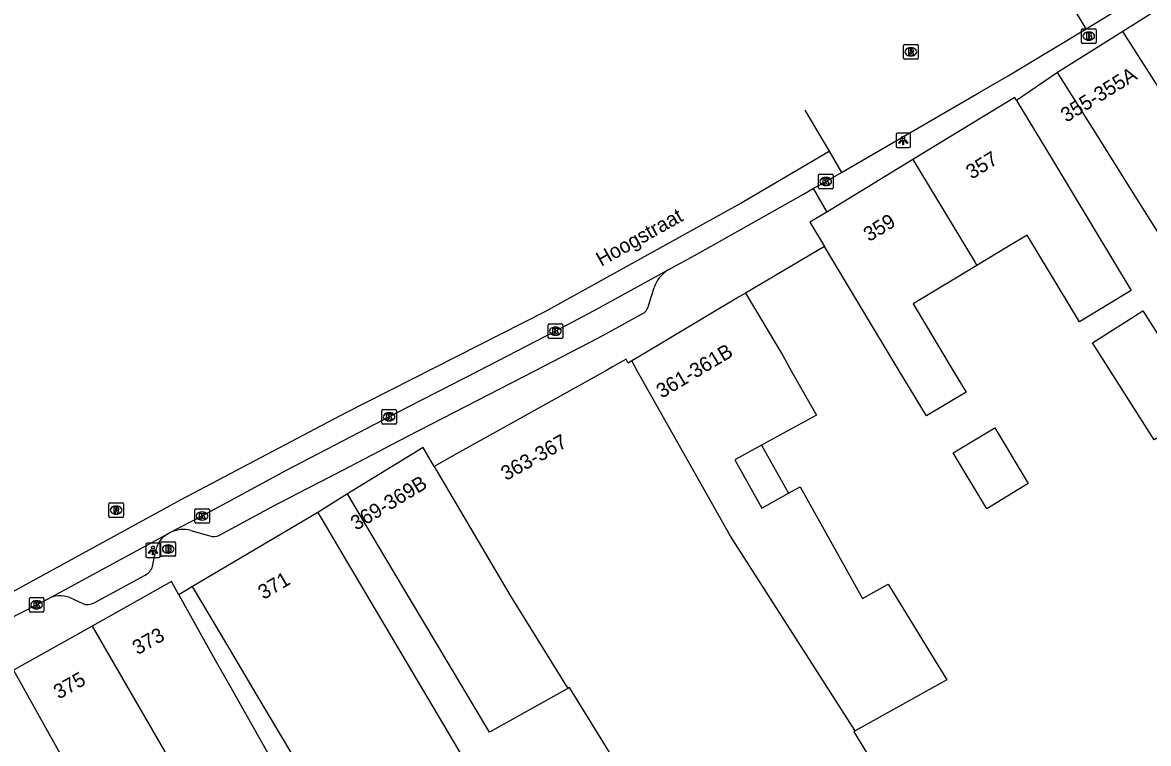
# Model space of a CAD drawing. Extents: x 159822 to 160765, y 380693 to 381634.
# Drawn here: x 159932.4 to 160009.6, y 381474.4 to 381523.9 of the extents above; entities that cross this region are included whole.
import ezdxf

# ---------------------------------------------------------------- set-up
doc = ezdxf.new("R2010")
doc.units = 0
for name, color, linetype in [('IMGEO_Brandkraan', 7, 'Continuous'), ('IMGEO_Kolk', 7, 'Continuous'), ('IMGEO_Lichtpunt', 7, 'Continuous'), ('IMGEO_Openbare_ruimte_label', 7, 'Continuous'), ('IMGEO_Pand', 7, 'Continuous'), ('IMGEO_Pand_nummerreeks', 7, 'Continuous'), ('IMGEO_Rijbaan_lokaal_gesloten', 7, 'Continuous'), ('IMGEO_Rijbaan_lokaal_open', 7, 'Continuous'), ('IMGEO_Rioolput', 7, 'Continuous'), ('IMGEO_Voetpad_open', 7, 'Continuous')]:
    doc.layers.add(name, color=color, linetype=linetype)

msp = doc.modelspace()

# ---------------------------------------------------------------- linework, layer by layer
at = {"layer": 'IMGEO_Brandkraan'}
for p, q in [((160005.025, 381522.533), (160005.025, 381523.385)), ((160005.1, 381523.459), (160005.952, 381523.459)), ((160005.513, 381523.239), (160005.538, 381523.239)), ((160006.026, 381523.385), (160006.026, 381522.533)), ((160005.952, 381522.459), (160005.1, 381522.459)), ((160005.536, 381522.679), (160005.511, 381522.679)), ((159941.871, 381487.334), (159941.871, 381488.186)), ((159941.946, 381488.26), (159942.798, 381488.26)), ((159942.359, 381488.04), (159942.384, 381488.04)), ((159942.872, 381488.186), (159942.872, 381487.334)), ((159942.798, 381487.26), (159941.946, 381487.26)), ((159942.382, 381487.48), (159942.357, 381487.48))]:
    msp.add_line(p, q, dxfattribs=at)
for points in [[(160005.025, 381522.533), (160005.025, 381523.385)], [(160005.1, 381523.459), (160005.952, 381523.459)], [(160005.373, 381523.159), (160005.373, 381522.759), (160005.586, 381522.759)], [(160005.604, 381523.159), (160005.373, 381523.159)], [(160005.552, 381523.078), (160005.498, 381523.078), (160005.498, 381523.002)], [(160005.498, 381523.002), (160005.551, 381523.002)], [(160005.56, 381522.926), (160005.498, 381522.926), (160005.498, 381522.845)], [(160005.498, 381522.845), (160005.56, 381522.845)], [(160006.026, 381523.385), (160006.026, 381522.533)], [(160005.952, 381522.459), (160005.1, 381522.459)], [(159941.871, 381487.334), (159941.871, 381488.186)], [(159941.946, 381488.26), (159942.798, 381488.26)], [(159942.219, 381487.96), (159942.219, 381487.56), (159942.432, 381487.56)], [(159942.45, 381487.96), (159942.219, 381487.96)], [(159942.872, 381488.186), (159942.872, 381487.334)], [(159942.798, 381487.26), (159941.946, 381487.26)], [(159942.398, 381487.879), (159942.344, 381487.879), (159942.344, 381487.803)], [(159942.344, 381487.803), (159942.397, 381487.803)], [(159942.406, 381487.727), (159942.344, 381487.727), (159942.344, 381487.646)], [(159942.344, 381487.646), (159942.406, 381487.646)]]:
    msp.add_lwpolyline(points, dxfattribs=at)
for centre, radius, start, end in [((160005.102, 381523.383), 0.0765, 91.55205, 178.44795), ((160005.102, 381523.383), 0.0765, 91.55205, 178.44795), ((160005.553, 381523.04), 0.0379, 267.82845, 90.93552), ((160005.561, 381522.885), 0.0404, 269.87594, 90.50774), ((160005.592, 381523.01), 0.251, 268.66757, 293.53466), ((160005.608, 381523.014), 0.145, 59.4692, 91.53667), ((160005.633, 381523.061), 0.0922, 285.51372, 58.15012), ((160005.638, 381522.869), 0.105, 301.31148, 78.98903), ((160005.95, 381523.383), 0.0765, 1.55205, 88.44795), ((160005.95, 381523.383), 0.0765, 1.55205, 88.44795), ((160005.102, 381522.535), 0.0765, 181.55205, 268.44795), ((160005.102, 381522.535), 0.0765, 181.55205, 268.44795), ((160005.95, 381522.535), 0.0765, 271.55205, 358.44795), ((160005.95, 381522.535), 0.0765, 271.55205, 358.44795), ((159941.948, 381488.184), 0.0765, 91.55205, 178.44795), ((159941.948, 381488.184), 0.0765, 91.55205, 178.44795), ((159942.454, 381487.815), 0.145, 59.4692, 91.53667), ((159942.796, 381488.184), 0.0765, 1.55205, 88.44795), ((159942.796, 381488.184), 0.0765, 1.55205, 88.44795), ((159941.948, 381487.336), 0.0765, 181.55205, 268.44795), ((159941.948, 381487.336), 0.0765, 181.55205, 268.44795), ((159942.399, 381487.841), 0.0379, 267.82845, 90.93552), ((159942.407, 381487.686), 0.0404, 269.87594, 90.50774), ((159942.438, 381487.811), 0.251, 268.66757, 293.53466), ((159942.479, 381487.862), 0.0922, 285.51372, 58.15012), ((159942.484, 381487.67), 0.105, 301.31148, 78.98903), ((159942.796, 381487.336), 0.0765, 271.55205, 358.44795), ((159942.796, 381487.336), 0.0765, 271.55205, 358.44795)]:
    msp.add_arc(centre, radius, start, end, dxfattribs=at)
for centre, major_axis, ratio, start_param, end_param in [((160005.512, 381522.959), (-0.387, 0.002), 0.722429, 4.712389, 7.853982), ((160005.537, 381522.959), (-0.39, 0.002), 0.717154, 1.570796, 4.712389), ((159942.358, 381487.76), (-0.387, 0.002), 0.722429, 4.712389, 7.853982), ((159942.383, 381487.76), (-0.39, 0.002), 0.717154, 1.570796, 4.712389)]:
    msp.add_ellipse(centre, major_axis=major_axis, ratio=ratio, start_param=start_param, end_param=end_param, dxfattribs=at)
at = {"layer": 'IMGEO_Kolk'}
for p, q in [((159987.059, 381513.483), (159987.911, 381513.483)), ((159986.984, 381512.557), (159986.984, 381513.409)), ((159987.495, 381512.703), (159987.47, 381512.703)), ((159987.472, 381513.263), (159987.497, 381513.263)), ((159987.985, 381513.409), (159987.985, 381512.557)), ((159987.911, 381512.483), (159987.059, 381512.483)), ((159968.432, 381502.28), (159968.432, 381503.132)), ((159968.507, 381503.206), (159969.359, 381503.206)), ((159968.92, 381502.986), (159968.945, 381502.986)), ((159969.433, 381503.132), (159969.433, 381502.28)), ((159969.359, 381502.206), (159968.507, 381502.206)), ((159968.943, 381502.426), (159968.918, 381502.426)), ((159957.023, 381496.41), (159957.023, 381497.262)), ((159957.098, 381497.336), (159957.95, 381497.336)), ((159958.024, 381497.262), (159958.024, 381496.41)), ((159957.534, 381496.556), (159957.509, 381496.556)), ((159957.511, 381497.116), (159957.536, 381497.116)), ((159957.95, 381496.336), (159957.098, 381496.336)), ((159944.193, 381489.601), (159944.193, 381490.453)), ((159944.268, 381490.527), (159945.12, 381490.527)), ((159944.681, 381490.307), (159944.706, 381490.307)), ((159945.194, 381490.453), (159945.194, 381489.601)), ((159945.12, 381489.527), (159944.268, 381489.527)), ((159944.704, 381489.747), (159944.679, 381489.747)), ((159932.844, 381483.51), (159932.844, 381484.362)), ((159932.919, 381484.436), (159933.771, 381484.436)), ((159933.332, 381484.216), (159933.357, 381484.216)), ((159933.845, 381484.362), (159933.845, 381483.51)), ((159933.771, 381483.436), (159932.919, 381483.436)), ((159933.355, 381483.656), (159933.33, 381483.656))]:
    msp.add_line(p, q, dxfattribs=at)
for points in [[(159987.059, 381513.483), (159987.911, 381513.483)], [(159986.984, 381512.557), (159986.984, 381513.409)], [(159987.305, 381513.183), (159987.428, 381513.183), (159987.428, 381513.032), (159987.558, 381513.183), (159987.722, 381513.183), (159987.576, 381513.032), (159987.729, 381512.783), (159987.577, 381512.783), (159987.492, 381512.947), (159987.428, 381512.88), (159987.428, 381512.783), (159987.305, 381512.783), (159987.305, 381513.183)], [(159987.985, 381513.409), (159987.985, 381512.557)], [(159987.911, 381512.483), (159987.059, 381512.483)], [(159968.432, 381502.28), (159968.432, 381503.132)], [(159968.507, 381503.206), (159969.359, 381503.206)], [(159968.753, 381502.906), (159968.876, 381502.906), (159968.876, 381502.755), (159969.006, 381502.906), (159969.17, 381502.906), (159969.024, 381502.755), (159969.177, 381502.506), (159969.025, 381502.506), (159968.94, 381502.67), (159968.876, 381502.603), (159968.876, 381502.506), (159968.753, 381502.506), (159968.753, 381502.906)], [(159969.433, 381503.132), (159969.433, 381502.28)], [(159969.359, 381502.206), (159968.507, 381502.206)], [(159957.023, 381496.41), (159957.023, 381497.262)], [(159957.098, 381497.336), (159957.95, 381497.336)], [(159958.024, 381497.262), (159958.024, 381496.41)], [(159957.344, 381497.036), (159957.467, 381497.036), (159957.467, 381496.885), (159957.597, 381497.036), (159957.761, 381497.036), (159957.615, 381496.885), (159957.768, 381496.636), (159957.616, 381496.636), (159957.531, 381496.8), (159957.467, 381496.733), (159957.467, 381496.636), (159957.344, 381496.636), (159957.344, 381497.036)], [(159957.95, 381496.336), (159957.098, 381496.336)], [(159944.193, 381489.601), (159944.193, 381490.453)], [(159944.268, 381490.527), (159945.12, 381490.527)], [(159945.194, 381490.453), (159945.194, 381489.601)], [(159945.12, 381489.527), (159944.268, 381489.527)], [(159944.514, 381490.227), (159944.637, 381490.227), (159944.637, 381490.076), (159944.767, 381490.227), (159944.931, 381490.227), (159944.785, 381490.076), (159944.938, 381489.827), (159944.786, 381489.827), (159944.701, 381489.991), (159944.637, 381489.924), (159944.637, 381489.827), (159944.514, 381489.827), (159944.514, 381490.227)], [(159932.844, 381483.51), (159932.844, 381484.362)], [(159932.919, 381484.436), (159933.771, 381484.436)], [(159933.165, 381484.136), (159933.288, 381484.136), (159933.288, 381483.985), (159933.418, 381484.136), (159933.582, 381484.136), (159933.436, 381483.985), (159933.589, 381483.736), (159933.437, 381483.736), (159933.352, 381483.9), (159933.288, 381483.833), (159933.288, 381483.736), (159933.165, 381483.736), (159933.165, 381484.136)], [(159933.845, 381484.362), (159933.845, 381483.51)], [(159933.771, 381483.436), (159932.919, 381483.436)]]:
    msp.add_lwpolyline(points, dxfattribs=at)
for centre, start, end in [((159987.061, 381513.407), 91.55205, 178.44795), ((159987.061, 381513.407), 91.55205, 178.44795), ((159987.909, 381513.407), 1.55205, 88.44795), ((159987.909, 381513.407), 1.55205, 88.44795), ((159987.061, 381512.559), 181.55205, 268.44795), ((159987.061, 381512.559), 181.55205, 268.44795), ((159987.909, 381512.559), 271.55205, 358.44795), ((159987.909, 381512.559), 271.55205, 358.44795), ((159968.509, 381503.13), 91.55205, 178.44795), ((159968.509, 381503.13), 91.55205, 178.44795), ((159969.357, 381503.13), 1.55205, 88.44795), ((159969.357, 381503.13), 1.55205, 88.44795), ((159968.509, 381502.282), 181.55205, 268.44795), ((159968.509, 381502.282), 181.55205, 268.44795), ((159969.357, 381502.282), 271.55205, 358.44795), ((159969.357, 381502.282), 271.55205, 358.44795), ((159957.1, 381497.26), 91.55205, 178.44795), ((159957.1, 381497.26), 91.55205, 178.44795), ((159957.948, 381497.26), 1.55205, 88.44795), ((159957.948, 381497.26), 1.55205, 88.44795), ((159957.1, 381496.412), 181.55205, 268.44795), ((159957.1, 381496.412), 181.55205, 268.44795), ((159957.948, 381496.412), 271.55205, 358.44795), ((159957.948, 381496.412), 271.55205, 358.44795), ((159944.27, 381490.451), 91.55205, 178.44795), ((159944.27, 381490.451), 91.55205, 178.44795), ((159945.118, 381490.451), 1.55205, 88.44795), ((159945.118, 381490.451), 1.55205, 88.44795), ((159944.27, 381489.603), 181.55205, 268.44795), ((159944.27, 381489.603), 181.55205, 268.44795), ((159945.118, 381489.603), 271.55205, 358.44795), ((159945.118, 381489.603), 271.55205, 358.44795), ((159932.921, 381484.36), 91.55205, 178.44795), ((159932.921, 381484.36), 91.55205, 178.44795), ((159933.769, 381484.36), 1.55205, 88.44795), ((159933.769, 381484.36), 1.55205, 88.44795), ((159932.921, 381483.512), 181.55205, 268.44795), ((159932.921, 381483.512), 181.55205, 268.44795), ((159933.769, 381483.512), 271.55205, 358.44795), ((159933.769, 381483.512), 271.55205, 358.44795)]:
    msp.add_arc(centre, 0.0765, start, end, dxfattribs=at)
for centre, major_axis, ratio, start_param, end_param in [((159987.471, 381512.983), (-0.387, 0.002), 0.722429, 4.712389, 7.853982), ((159987.496, 381512.983), (-0.39, 0.002), 0.717154, 1.570796, 4.712389), ((159968.919, 381502.706), (-0.387, 0.002), 0.722429, 4.712389, 7.853982), ((159968.944, 381502.706), (-0.39, 0.002), 0.717154, 1.570796, 4.712389), ((159957.51, 381496.836), (-0.387, 0.002), 0.722429, 4.712389, 7.853982), ((159957.535, 381496.836), (-0.39, 0.002), 0.717154, 1.570796, 4.712389), ((159944.68, 381490.027), (-0.387, 0.002), 0.722429, 4.712389, 7.853982), ((159944.705, 381490.027), (-0.39, 0.002), 0.717154, 1.570796, 4.712389), ((159933.331, 381483.936), (-0.387, 0.002), 0.722429, 4.712389, 7.853982), ((159933.356, 381483.936), (-0.39, 0.002), 0.717154, 1.570796, 4.712389)]:
    msp.add_ellipse(centre, major_axis=major_axis, ratio=ratio, start_param=start_param, end_param=end_param, dxfattribs=at)
at = {"layer": 'IMGEO_Lichtpunt'}
for p, q in [((159992.302, 381516.205), (159992.302, 381515.398)), ((159992.302, 381516.205), (159992.302, 381515.398)), ((159993.204, 381516.3), (159992.396, 381516.3)), ((159993.204, 381516.3), (159992.396, 381516.3)), ((159993.298, 381515.398), (159993.298, 381516.205)), ((159993.298, 381515.398), (159993.298, 381516.205)), ((159992.396, 381515.304), (159993.204, 381515.304)), ((159992.396, 381515.304), (159993.204, 381515.304)), ((159940.826, 381488.072), (159940.826, 381487.265)), ((159940.826, 381488.072), (159940.826, 381487.265)), ((159941.728, 381488.167), (159940.92, 381488.167)), ((159941.728, 381488.167), (159940.92, 381488.167)), ((159941.822, 381487.265), (159941.822, 381488.072)), ((159941.822, 381487.265), (159941.822, 381488.072)), ((159940.92, 381487.171), (159941.728, 381487.171)), ((159940.92, 381487.171), (159941.728, 381487.171))]:
    msp.add_line(p, q, dxfattribs=at)
for points in [[(159992.676, 381515.869), (159992.715, 381515.841), (159992.527, 381515.579), (159992.489, 381515.606), (159992.676, 381515.869)], [(159992.778, 381515.821), (159992.825, 381515.821), (159992.825, 381515.499), (159992.778, 381515.499), (159992.778, 381515.821)], [(159992.888, 381515.841), (159992.926, 381515.868), (159993.113, 381515.606), (159993.074, 381515.578), (159992.888, 381515.841)], [(159941.2, 381487.736), (159941.239, 381487.708), (159941.051, 381487.446), (159941.013, 381487.473), (159941.2, 381487.736)], [(159941.302, 381487.688), (159941.349, 381487.688), (159941.349, 381487.366), (159941.302, 381487.366), (159941.302, 381487.688)], [(159941.412, 381487.708), (159941.45, 381487.735), (159941.637, 381487.473), (159941.598, 381487.445), (159941.412, 381487.708)]]:
    msp.add_lwpolyline(points, dxfattribs=at)
for centre in [(159992.801, 381516.003), (159941.325, 381487.87)]:
    msp.add_circle(centre, 0.0994, dxfattribs=at)
for centre, start, end in [((159992.396, 381516.205), 90, 180), ((159992.396, 381516.205), 90, 180), ((159993.204, 381516.205), 0, 90), ((159993.204, 381516.205), 0, 90), ((159992.396, 381515.398), 180, 270), ((159992.396, 381515.398), 180, 270), ((159993.204, 381515.398), 270, 0), ((159993.204, 381515.398), 270, 360), ((159940.92, 381488.072), 90, 180), ((159940.92, 381488.072), 90, 180), ((159941.728, 381488.072), 0, 90), ((159941.728, 381488.072), 0, 90), ((159940.92, 381487.265), 180, 270), ((159940.92, 381487.265), 180, 270), ((159941.728, 381487.265), 270, 0), ((159941.728, 381487.265), 270, 360)]:
    msp.add_arc(centre, 0.0946, start, end, dxfattribs=at)
at = {"layer": 'IMGEO_Pand'}
for points in [[(160014.641, 381527.565), (160014.041, 381527.185), (160007.851, 381523.273)], [(160007.851, 381523.273), (160003.39, 381520.454)], [(160012.891, 381515.416), (160007.851, 381523.273)], [(160023.877, 381495.766), (160020.325, 381493.529), (160016.251, 381500), (160008.062, 381513.006), (160006.05, 381516.226), (160003.39, 381520.454)], [(160000.573, 381518.549), (160000.452, 381518.75), (160000, 381518.475), (159993.462, 381514.491)], [(160000.573, 381518.549), (160003.033, 381514.469), (160008.438, 381505.504), (160004.88, 381503.359), (160001.299, 381509.3), (160000, 381508.517), (159997.853, 381507.222)], [(159993.462, 381514.491), (159987.549, 381510.887)], [(159993.462, 381514.491), (159997.728, 381507.415), (159997.853, 381507.222)], [(159987.549, 381510.887), (159986.387, 381510.179), (159987.393, 381508.511)], [(159997.853, 381507.222), (159993.468, 381504.578), (159996.217, 381500), (159997.103, 381498.525), (159994.391, 381496.892), (159992.52, 381500), (159989.934, 381504.296), (159987.393, 381508.511)], [(159981.967, 381505.328), (159981.489, 381505.041), (159974.614, 381500.916), (159974.177, 381500.666)], [(159981.967, 381505.328), (159984.528, 381501.034), (159985.116, 381500), (159986.856, 381496.937), (159983.074, 381494.884)], [(160010.01, 381495.246), (160005.773, 381501.901), (160009.243, 381504.11), (160013.556, 381497.336), (160010.01, 381495.246)], [(159974.177, 381500.666), (159973.927, 381500.523), (159973.777, 381500.79), (159972.86, 381500.263), (159972.389, 381500), (159962.159, 381494.282), (159960.772, 381493.507), (159960.626, 381493.425)], [(159989.504, 381475.275), (159980.953, 381488.644), (159974.553, 381500), (159974.177, 381500.666)], [(159998.526, 381490.509), (159996.224, 381494.373), (159999.082, 381496.075), (160001.357, 381492.256), (159998.526, 381490.509)], [(159960.626, 381493.425), (159959.863, 381494.724), (159954.663, 381491.547)], [(159983.074, 381494.884), (159981.233, 381493.885), (159983.091, 381490.562), (159984.919, 381491.584)], [(159983.074, 381494.884), (159984.919, 381491.584)], [(159960.626, 381493.425), (159965.835, 381484.562), (159969.777, 381478.193)], [(159984.919, 381491.584), (159985.721, 381492.032), (159990.003, 381484.372), (159991.772, 381485.36), (159995.785, 381478.787), (159989.504, 381475.275)], [(159969.777, 381478.193), (159964.414, 381475.194), (159957.17, 381487.344), (159954.663, 381491.547)], [(159952.629, 381490.261), (159955.179, 381485.96), (159963.025, 381472.729), (159965.093, 381469.241), (159960.942, 381466.779), (159958.874, 381470.267), (159956.844, 381473.69), (159952.421, 381471.068), (159948.483, 381477.709), (159946.592, 381480.898), (159944.042, 381485.199)], [(159952.629, 381490.261), (159944.042, 381485.199)], [(159943.094, 381484.616), (159942.586, 381485.527), (159937.151, 381482.476)], [(159943.094, 381484.616), (159945.573, 381480.173), (159946.58, 381478.421), (159951.006, 381470.546), (159949.258, 381469.678), (159949.545, 381469.151)], [(159937.151, 381482.476), (159931.762, 381479.45)], [(159937.151, 381482.476), (159945.986, 381467.216)], [(159931.762, 381479.45), (159935.718, 381472.36)], [(159989.504, 381475.275), (159989.4, 381475.217), (159996.739, 381463.236), (159983.663, 381455.926), (159969.908, 381478.266), (159969.777, 381478.193)]]:
    msp.add_lwpolyline(points, dxfattribs=at)
at = {"layer": 'IMGEO_Rijbaan_lokaal_gesloten'}
for points in [[(160005.352, 381523.447), (160008.094, 381525.124), (160011.607, 381527.279), (160015.114, 381529.478), (160015.964, 381530.015), (160025.094, 381535.855), (160026.107, 381536.518), (160029.867, 381538.931), (160042.646, 381547.078), (160046.466, 381549.511)], [(160005.352, 381523.447), (160004.479, 381524.903)], [(159988.557, 381513.599), (159998.058, 381519.1), (160000, 381520.239), (160001.104, 381520.886), (160005.352, 381523.447)], [(159986.055, 381517.88), (159987.706, 381515.056)], [(159825.741, 381425.114), (159830.92, 381427.938), (159857.238, 381442.392), (159881.509, 381456.068), (159898.004, 381465.69), (159907.745, 381471.382), (159914.294, 381475.19), (159926.777, 381482.151), (159943.271, 381491.16), (159954.568, 381497.138), (159968.238, 381504.058), (159981.458, 381511.387), (159987.706, 381515.056)], [(159987.706, 381515.056), (159988.557, 381513.599)]]:
    msp.add_lwpolyline(points, dxfattribs=at)
at = {"layer": 'IMGEO_Rijbaan_lokaal_open'}
for points in [[(159986.624, 381512.501), (159987.48, 381512.983), (159988.557, 381513.599)], [(159976.668, 381506.91), (159978.262, 381507.78), (159979.817, 381508.648), (159985.965, 381512.122), (159986.624, 381512.501)], [(159942.487, 381488.885), (159944.694, 381490.028), (159948.597, 381492.138), (159950.445, 381493.14), (159958.832, 381497.52), (159963.66, 381500), (159968.928, 381502.706), (159971.586, 381504.125), (159976.668, 381506.91)], [(159934.089, 381484.332), (159942.338, 381488.805)], [(159942.338, 381488.805), (159942.487, 381488.885)], [(159928.594, 381481.394), (159931.412, 381482.953), (159933.344, 381483.936), (159934.089, 381484.332)]]:
    msp.add_lwpolyline(points, dxfattribs=at)
at = {"layer": 'IMGEO_Rioolput'}
for p, q in [((159992.816, 381521.452), (159992.816, 381522.304)), ((159992.891, 381522.378), (159993.743, 381522.378)), ((159993.304, 381522.158), (159993.329, 381522.158)), ((159993.817, 381522.304), (159993.817, 381521.452)), ((159993.743, 381521.378), (159992.891, 381521.378)), ((159993.327, 381521.598), (159993.302, 381521.598)), ((159938.299, 381490.006), (159938.299, 381490.858)), ((159938.374, 381490.932), (159939.226, 381490.932)), ((159938.787, 381490.712), (159938.812, 381490.712)), ((159939.3, 381490.858), (159939.3, 381490.006)), ((159939.226, 381489.932), (159938.374, 381489.932)), ((159938.81, 381490.152), (159938.785, 381490.152))]:
    msp.add_line(p, q, dxfattribs=at)
for points in [[(159992.816, 381521.452), (159992.816, 381522.304)], [(159992.891, 381522.378), (159993.743, 381522.378)], [(159993.405, 381522.076), (159993.153, 381522.078), (159993.153, 381521.678)], [(159993.331, 381521.997), (159993.277, 381521.997), (159993.277, 381521.916)], [(159993.817, 381522.304), (159993.817, 381521.452)], [(159993.743, 381521.378), (159992.891, 381521.378)], [(159993.153, 381521.678), (159993.277, 381521.678), (159993.277, 381521.84), (159993.288, 381521.84)], [(159993.277, 381521.916), (159993.329, 381521.916)], [(159993.335, 381521.811), (159993.406, 381521.678), (159993.546, 381521.678), (159993.481, 381521.804)], [(159938.299, 381490.006), (159938.299, 381490.858)], [(159938.374, 381490.932), (159939.226, 381490.932)], [(159938.888, 381490.63), (159938.636, 381490.632), (159938.636, 381490.232)], [(159938.636, 381490.232), (159938.76, 381490.232), (159938.76, 381490.394), (159938.771, 381490.394)], [(159938.814, 381490.551), (159938.76, 381490.551), (159938.76, 381490.47)], [(159938.76, 381490.47), (159938.812, 381490.47)], [(159938.818, 381490.365), (159938.889, 381490.232), (159939.029, 381490.232), (159938.964, 381490.358)], [(159939.3, 381490.858), (159939.3, 381490.006)], [(159939.226, 381489.932), (159938.374, 381489.932)]]:
    msp.add_lwpolyline(points, dxfattribs=at)
for centre, radius, start, end in [((159992.893, 381522.302), 0.0765, 91.55205, 178.44795), ((159992.893, 381522.302), 0.0765, 91.55205, 178.44795), ((159993.337, 381521.901), 0.0964, 77.00612, 93.18647), ((159993.351, 381521.958), 0.0378, 276.66336, 79.67722), ((159993.404, 381521.966), 0.109, 350.36119, 89.41601), ((159993.402, 381521.966), 0.112, 277.58423, 350.98172), ((159993.741, 381522.302), 0.0765, 1.55205, 88.44795), ((159993.741, 381522.302), 0.0765, 1.55205, 88.44795), ((159992.893, 381521.454), 0.0765, 181.55205, 268.44795), ((159992.893, 381521.454), 0.0765, 181.55205, 268.44795), ((159993.287, 381521.787), 0.0533, 26.02933, 88.69889), ((159993.313, 381522.105), 0.19, 274.7715, 282.96867), ((159993.386, 381521.751), 0.108, 29.51342, 73.79051), ((159993.741, 381521.454), 0.0765, 271.55205, 358.44795), ((159993.741, 381521.454), 0.0765, 271.55205, 358.44795), ((159938.376, 381490.856), 0.0765, 91.55205, 178.44795), ((159938.376, 381490.856), 0.0765, 91.55205, 178.44795), ((159938.77, 381490.341), 0.0533, 26.02933, 88.69889), ((159938.796, 381490.659), 0.19, 274.7715, 282.96867), ((159938.82, 381490.455), 0.0964, 77.00612, 93.18647), ((159938.834, 381490.512), 0.0378, 276.66336, 79.67722), ((159938.887, 381490.52), 0.109, 350.36119, 89.41601), ((159938.885, 381490.52), 0.112, 277.58423, 350.98172), ((159938.869, 381490.305), 0.108, 29.51342, 73.79051), ((159939.224, 381490.856), 0.0765, 1.55205, 88.44795), ((159939.224, 381490.856), 0.0765, 1.55205, 88.44795), ((159938.376, 381490.008), 0.0765, 181.55205, 268.44795), ((159938.376, 381490.008), 0.0765, 181.55205, 268.44795), ((159939.224, 381490.008), 0.0765, 271.55205, 358.44795), ((159939.224, 381490.008), 0.0765, 271.55205, 358.44795)]:
    msp.add_arc(centre, radius, start, end, dxfattribs=at)
for centre, major_axis, ratio, start_param, end_param in [((159993.303, 381521.878), (-0.387, 0.002), 0.722429, 4.712389, 7.853982), ((159993.328, 381521.878), (-0.39, 0.002), 0.717154, 1.570796, 4.712389), ((159938.786, 381490.432), (-0.387, 0.002), 0.722429, 4.712389, 7.853982), ((159938.811, 381490.432), (-0.39, 0.002), 0.717154, 1.570796, 4.712389)]:
    msp.add_ellipse(centre, major_axis=major_axis, ratio=ratio, start_param=start_param, end_param=end_param, dxfattribs=at)
at = {"layer": 'IMGEO_Voetpad_open'}
for points in [[(160003.39, 381520.454), (160000.573, 381518.549)], [(159986.624, 381512.501), (159987.549, 381510.887)], [(159987.393, 381508.511), (159981.967, 381505.328)], [(159975.329, 381504.45), (159975.714, 381505.698)], [(159945.881, 381488.71), (159949.476, 381490.648), (159951.247, 381491.566), (159954.354, 381493.179), (159958.806, 381495.496), (159967.521, 381500), (159971.281, 381501.943), (159972.195, 381502.423), (159974.85, 381503.875)], [(159954.663, 381491.547), (159952.629, 381490.261)], [(159943.932, 381489.035), (159945.219, 381488.668)], [(159941.302, 381486.572), (159941.496, 381487.563)], [(159937.289, 381484.064), (159940.8, 381485.977)], [(159944.042, 381485.199), (159943.094, 381484.616)], [(159935.618, 381484.431), (159936.506, 381484.013)]]:
    msp.add_lwpolyline(points, dxfattribs=at)
for centre, radius, start, end in [((159977.792, 381505.043), 2.179, 121.06629, 162.51911), ((159974.474, 381504.676), 0.885, 295.1819, 345.22657), ((159943.205, 381487.311), 1.728, 120.12688, 171.60338), ((159943.411, 381487.017), 2.084, 75.52608, 116.32678), ((159945.499, 381489.486), 0.865, 251.08087, 296.17956), ((159940.275, 381486.93), 1.088, 298.87955, 340.81197), ((159934.963, 381482.687), 1.863, 69.41928, 117.98998), ((159936.838, 381484.95), 0.994, 250.4836, 296.96969)]:
    msp.add_arc(centre, radius, start, end, dxfattribs=at)

# ---------------------------------------------------------------- texts
at = {"layer": 'IMGEO_Openbare_ruimte_label'}
msp.add_text('Hoogstraat', height=1, rotation=29.33279, dxfattribs=at).set_placement((159972.08, 381507.124))
at = {"layer": 'IMGEO_Pand_nummerreeks'}
for s, rotation, p in [('355-355A', 31.61736, (160003.99, 381517.005)), ('357', 31.35613, (159997.487, 381513.102)), ('359', 31.35886, (159990.455, 381508.816)), ('361-361B', 30.89961, (159976.232, 381498.072)), ('363-367', 29.2495, (159965.549, 381492.423)), ('369-369B', 31.2262, (159955.269, 381489.003)), ('371', 30.51917, (159948.911, 381484.262)), ('373', 29.31167, (159940.272, 381480.467)), ('375', 29.31166, (159934.86, 381477.428))]:
    msp.add_text(s, height=1, rotation=rotation, dxfattribs=at).set_placement(p)

doc.saveas('drawing.dxf')
